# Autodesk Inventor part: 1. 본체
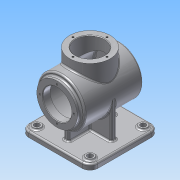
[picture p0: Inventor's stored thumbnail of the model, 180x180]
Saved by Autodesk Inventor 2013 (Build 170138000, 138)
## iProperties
Created: 2015-07
Part Number: 1. 본체
Material: 알루미늄 6061
Document SubType Name: Modeling
Designer: Administrator
Density: 2.71 g/cm^3
Mass: 1277.38 g
Surface Area: 1268.5 cm^2
Volume: 471.358 cm^3
Author: Administrator
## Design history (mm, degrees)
sketch "스케치1"
  geometry: C1 r 45 at (0, 0); 1 further point
  constraints: 1 centre point, 1 coincident
  dimensions: "d0" = 90 diameter of C1
extrude "돌출1" new body sketch "스케치1" distance "d2" = 110; taper "d3" = 0 deg
sketch "스케치2"
  geometry: C1 r 45 at (0, 0) reference; C2 r 38 at (0, 0); 1 further point
  constraints: 1 centre point, 1 coincident
  dimensions: "d4" = 76 diameter of C2
extrude "돌출2" join sketch "스케치2" distance "d6" = 7; taper "d7" = 0 deg
node "작업점1"
  node "작업 평면1"
  node "작업 평면2"
sketch "스케치3"
  geometry: C1 r 38 at (0, 55); 2 further points
  constraints: 1 centre point, 1 coincident
  dimensions: "d9" = 76 diameter of C1
extrude "돌출3" join sketch "스케치3" stored distance "d11" = 7; taper "d12" = 0 deg
sketch "스케치4"
  geometry: C1 r 38 at (0, 0) reference; C2 r 27 at (0, 0); 1 further point
  constraints: 1 centre point, 1 coincident
  dimensions: "d13" = 54 diameter of C2
extrude "돌출4" cut sketch "스케치4" distance "d15" = 62; taper "d16" = 0 deg
node "작업 평면3"
sketch "스케치5"
  geometry: L1 (-38, 24.104)-(-38, 62) reference; L2 (-38, 62)-(-27, 62) reference; L3 (-27, 62)-(-27, 0) reference; L4 (-27, 0)-(27, 0) reference; L5 (27, 0)-(27, 62) reference; L6 (27, 62)-(38, 62) reference; L7 (38, 62)-(38, 24.104) reference; L8 (-65, -68)-(65, -68); L9 (65, -68)-(65, -78); L10 (65, -78)-(-65, -78); L11 (-65, -78)-(-65, -68); A1 r 45 centre (0, 0) between (-38, 24.104) and (38, 24.104) reference; 3 further points
  constraints: 8 end point, 2 parallel, 1 horizontal, 1 midpoint, 1 perpendicular, 1 point on circle, 1 vertical alignment
  dimensions: "d18" = 130 distance of L9.end L10.end; "d20" = 10 distance of L8.end L9.end; "d21" = 140 distance between parallel lines of L10 L6
extrude "돌출5" join sketch "스케치5" distance "d22" = 65; taper "d24" = 0 deg; dims "d23" = 65, "d25" = 0
sketch "스케치7"
  geometry: L1 (20, 70)-(110, 70); L2 (110, 70)-(110, 60); L3 (110, 60)-(20, 60); L4 (20, 60)-(20, 70); L5 (130, 0)-(130, 130) reference; L6 (130, 130)-(0, 130) reference; 5 further points
  constraints: 8 end point, 4 midpoint, 2 parallel, 1 horizontal, 1 horizontal alignment, 1 perpendicular, 1 vertical alignment
  dimensions: "d29" = 90 distance of L1.start L1.end; "d31" = 10 distance of L3.end L1.start
extrude "돌출6" join sketch "스케치7" stored distance "d32" = 65; taper "d33" = 0 deg
sketch "스케치8"
  geometry: L1 (20, 60)-(20, 70) reference; L2 (20, 70)-(110, 70) reference; L3 (110, 70)-(110, 60) reference; L4 (110, 60)-(20, 60) reference; L5 (0, 130)-(130, 130) reference; L6 (130, 130)-(130, 0) reference; L7 (130, 0)-(0, 0) reference; L8 (0, 0)-(0, 130) reference; L9 (60, 110)-(70, 110); L10 (70, 110)-(70, 20); L11 (70, 20)-(60, 20); L12 (60, 20)-(60, 110); 5 further points
  constraints: 8 end point, 4 midpoint, 2 parallel, 1 horizontal, 1 horizontal alignment, 1 perpendicular, 1 vertical alignment
  dimensions: "d34" = 90 distance of L9.end L10.end; "d36" = 10 distance of L9.start L9.end
extrude "돌출7" join sketch "스케치8" stored distance "d37" = 65; taper "d38" = 0 deg
sketch "스케치9"
  geometry: L1 (38, 117)-(38, 110) reference; L2 (38, 110)-(45, 110) reference; L3 (45, 110)-(45, 93) reference; L4 (45, 93)-(62, 93) reference; L5 (62, 93)-(62, 82) reference; L6 (62, 82)-(0, 82) reference; L7 (0, 82)-(0, 28) reference; L8 (0, 28)-(62, 28) reference; L9 (62, 28)-(62, 17) reference; L10 (62, 17)-(45, 17) reference; L11 (45, 17)-(45, 0) reference; L12 (45, 0)-(-45, 0) reference; L13 (-45, 0)-(-45, 10) reference; L14 (-45, 10)-(-68, 10) reference; L15 (-68, 10)-(-68, -10) reference; L16 (-68, -10)-(-78, -10) reference; L17 (-78, -10)-(-78, 120) reference; L18 (-78, 120)-(-68, 120) reference; L19 (-68, 120)-(-68, 100) reference; L20 (-68, 100)-(-45, 100) reference; L21 (-45, 100)-(-45, 110) reference; L22 (-45, 110)-(-38, 110) reference; L23 (-38, 110)-(-38, 117) reference; L24 (-38, 117)-(38, 117) reference; L25 (0, 0)-(0, 117); L26 (27, 117)-(27, 103); L27 (27, 103)-(40, 103); L28 (40, 103)-(40, 7); L29 (40, 7)-(0, 7)
  constraints: 10 end point, 2 parallel, 2 perpendicular, 2 point on line, 1 midpoint
  dimensions: "d39" = 80 diameter of L28 L25; "d41" = 7 distance between parallel lines of L12 L29; "d42" = 54 diameter of L26 L25; "d43" = 14 distance of L26.start L26.end
revolve "회전1" sketch "스케치9" stored, may be unused: angle "d44" = 90 deg
fillet "모깎기1" dims "d45" = 3
chamfer "모따기1" distance "d46" = 1; stored, may be unused: second distance "d47" = 2, angle "d48" = 45 deg
fillet "모깎기2" dims "d49" = 15
sketch "스케치10"
  geometry: L1 (115, 115)-(115, 15) reference; L2 (100, 0)-(0, 0) reference; L3 (-15, 15)-(-15, 115) reference; L4 (0, 130)-(100, 130) reference; L5 (45, 20)-(45, 60) reference; L6 (45, 60)-(5, 60) reference; L7 (5, 60)-(5, 70) reference; L8 (5, 70)-(45, 70) reference; L9 (45, 70)-(45, 110) reference; L10 (45, 110)-(55, 110) reference; L11 (55, 110)-(55, 70) reference; L12 (55, 70)-(95, 70) reference; L13 (95, 70)-(95, 60) reference; L14 (95, 60)-(55, 60) reference; L15 (55, 60)-(55, 20) reference; L16 (55, 20)-(45, 20) reference; C1 r 7.5 at (0, 115); C2 r 7.5 at (100, 115); C3 r 7.5 at (0, 15); C4 r 7.5 at (100, 15); A1 r 15 centre (100, 115) between (115, 115) and (100, 130) reference; A2 r 15 centre (100, 15) between (100, 0) and (115, 15) reference; A3 r 15 centre (0, 15) between (-15, 15) and (0, 0) reference; A4 r 15 centre (0, 115) between (0, 130) and (-15, 115) reference; 1 further point
  constraints: 4 centre point, 4 coincident, 3 equal radius
  dimensions: "d50" = 15 diameter of C1
extrude "돌출8" join sketch "스케치10" distance "d52" = 3; taper "d53" = 0 deg
sketch "스케치11"
  geometry: L1 (45, 5)-(45, 45) reference; L2 (45, 45)-(5, 45) reference; L3 (5, 45)-(5, 55) reference; L4 (5, 55)-(45, 55) reference; L5 (45, 55)-(45, 95) reference; L6 (45, 95)-(55, 95) reference; L7 (55, 95)-(55, 55) reference; L8 (55, 55)-(95, 55) reference; L9 (95, 55)-(95, 45) reference; L10 (95, 45)-(55, 45) reference; L11 (55, 45)-(55, 5) reference; L12 (55, 5)-(45, 5) reference; C1 r 7.5 at (0, 0) reference; C2 r 7.5 at (0, 100) reference; C3 r 7.5 at (100, 100) reference; C4 r 7.5 at (100, 0) reference; 5 further points
  constraints: 4 coincident
hole "구멍1" sketch "스케치11" at (0, 100), (100, 100), (100, 0), (0, 0) diameter "d54" = 10; stored, may be unused: countersink angle "d58" = 90 deg, drill point angle "d60" = 118 deg; dims "d55" = 6, "d56" = 4, "d57" = 2, "d59" = 8
sketch "스케치12"
  geometry: C1 r 38 at (0, 0) reference; C2 r 28 at (0, 0) reference; 2 further points
  constraints: 1 vertical alignment
  dimensions: "d61" = 32 distance of point (0, 32) C1.centre
hole "구멍2" sketch "스케치12" at (0, 32) diameter "d62" = 3.459; stored, may be unused: countersink angle "d66" = 90 deg, drill point angle "d68" = 118 deg; dims "d63" = 8, "d64" = 4, "d65" = 2, "d67" = 10
sketch "스케치13"
  geometry: C1 r 38 at (0, 0) reference; C2 r 28 at (0, 0) reference; 2 further points
  constraints: 1 vertical alignment
  dimensions: "d72" = 32 distance of point (0, 0) point (0, 32)
hole "구멍3" sketch "스케치13" at (0, 32) diameter "d73" = 3.459; stored, may be unused: countersink angle "d77" = 90 deg, drill point angle "d79" = 118 deg; dims "d74" = 8, "d75" = 4, "d76" = 2, "d78" = 10
fillet "모깎기3" dims "d83" = 3
fillet "모깎기4" dims "d84" = 3
fillet "모깎기5" dims "d85" = 3
fillet "모깎기6" dims "d86" = 3
fillet "모깎기7" dims "d87" = 3
sketch "스케치14"
  geometry: C1 r 42 at (0, 0) reference; 2 further points
  constraints: 1 coincident, 1 other
feature "엠보싱1" sketch "스케치14" dims "d3" = 0, "d88" = 0.5, "d89" = 0
node "솔리드1"
pattern_circular "원형 패턴1" dims angle "d70" = 360 deg
pattern_circular "원형 패턴2" dims angle "d81" = 360 deg
node "투영된 루프1"
node "투영된 루프2"
node "투영된 루프3"
node "투영된 루프4"
node "투영된 루프5"
node "절단 모서리 투영1"
node "절단 모서리 투영3"
node "절단 모서리 투영4"
node "절단 모서리 투영5"
node "절단 모서리 투영6"
other parameters: "d8" = 62, "d17" = -78
